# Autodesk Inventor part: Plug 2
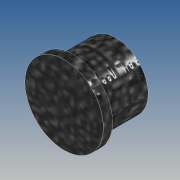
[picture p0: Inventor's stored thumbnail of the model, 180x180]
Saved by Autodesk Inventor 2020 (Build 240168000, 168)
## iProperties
Created: 2019-10
Part Number: Plug 2
Material: Generic
Document SubType Name: Modeling
Designer: yello
Density: 1 g/cm^3
Appearance: Default
Author: yello
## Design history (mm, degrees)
sketch "Sketch1"
  geometry: C1 r 4.25 at (0, 0); 1 further point
  constraints: 1 centre point, 1 coincident
  dimensions: "d0" = 8.5 diameter of C1
extrude "Extrusion1" new body sketch "Sketch1" distance "d1" = 1; taper "d2" = 0 deg
sketch "Sketch2"
  geometry: C1 r 3.5 at (0, 0); 1 further point
  constraints: 1 centre point, 1 coincident
  dimensions: "d3" = 7 diameter of C1
extrude "Extrusion2" join sketch "Sketch2" distance "d4" = 4.6; taper "d5" = 0 deg
body "Solid1"
